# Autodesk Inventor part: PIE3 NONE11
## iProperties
Shininess: 64.0
Length Units: 11269
Angle Units: 11279
Time Units: 11290
Mass Units: 11286
Length Display Precision: 3
Angle Display Precision: 2
Compacted: True
Part Number: PIE3 NONE11
Document SubType Name: Modeling
Created: 2004-08
Designer: John Blackburn
Manufacturer: Standard
Standards Organization: Custom
Density: 0.0
Volumn: 0.0
Area: 0.0
PropertySet Name: Model Information
Control State: 0
Master: False
Checked Out: False
Author: John Blackburn
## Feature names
1. Erst1
